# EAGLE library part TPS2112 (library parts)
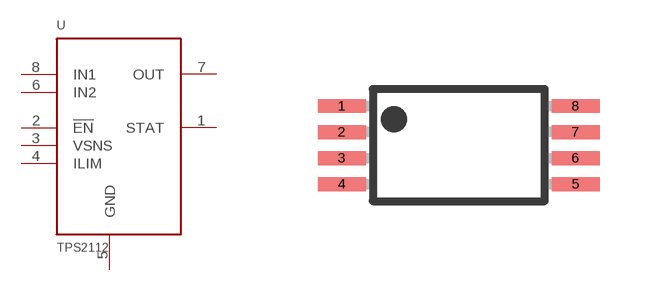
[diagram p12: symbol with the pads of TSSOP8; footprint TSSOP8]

Designator prefix -

## TPS2112  [TSSOP8]
1  STAT
2  !EN
3  VSNS
4  ILIM
5  GND
6  IN2
7  OUT
8  IN1

## Footprint TSSOP8 (pad centres in mm)
Plastic Small Outline
smd 1.2 x 0.35: 1 -2.925,0.975; 2 -2.925,0.325; 3 -2.925,-0.325; 4 -2.925,-0.975; 5 2.925,-0.975; 6 2.925,-0.325; 7 2.925,0.325; 8 2.925,0.975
